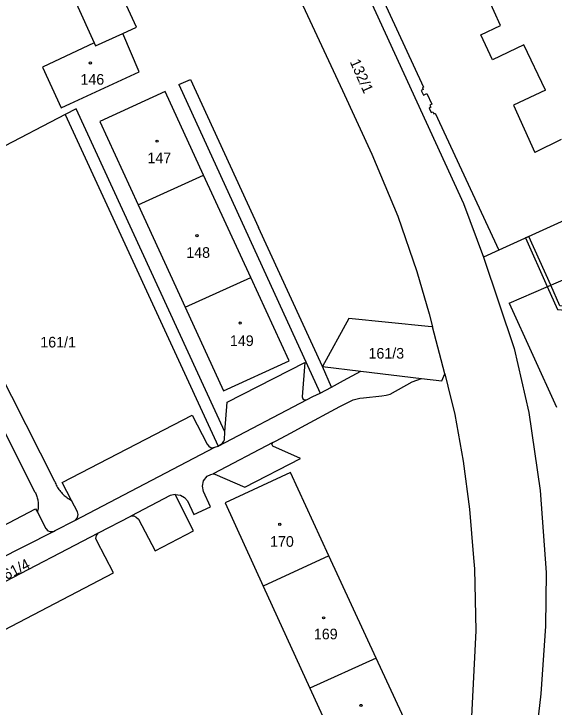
# Model space of a CAD drawing. Extents: x -869103 to -863415, y -1015889 to -1012477.
# Drawn here: x -867078.6 to -866992.3, y -1013913 to -1013802.3 of the extents above; entities that cross this region are included whole.
import ezdxf

# ---------------------------------------------------------------- set-up
doc = ezdxf.new("R2010")
doc.units = 0
for name, color, linetype in [('Hranice parcel', 7, 'Continuous'), ('Parcelní čísla', 7, 'Continuous'), ('Vnitřní kresba', 7, 'Continuous'), ('Věcná břemena k části', 7, 'Continuous'), ('Značky budov', 7, 'Continuous')]:
    doc.layers.add(name, color=color, linetype=linetype)

msp = doc.modelspace()

# ---------------------------------------------------------------- linework, layer by layer
at = {"layer": 'Hranice parcel'}
for p, q in [((-867011.35, -1013818.15), (-867001.17, -1013840.01)), ((-867058.76, -1013832.77), (-867048.3, -1013828.03)), ((-867040.77, -1013844.38), (-867048.3, -1013828.03)), ((-867058.76, -1013832.77), (-867051.25, -1013849.15)), ((-867001.17, -1013840.01), (-867003.6, -1013841.12)), ((-867003.6, -1013841.12), (-866998.7, -1013855.71)), ((-867051.25, -1013849.15), (-867040.77, -1013844.38)), ((-867009.8, -1013859.76), (-867011.73, -1013852.29)), ((-867023.17, -1013859.35), (-867013.48, -1013860.52)), ((-867028.29, -1013888.85), (-867038.77, -1013893.68)), ((-867020.72, -1013905.22), (-867028.29, -1013888.85)), ((-867038.77, -1013893.68), (-867031.32, -1013909.98)), ((-867020.72, -1013905.22), (-867031.32, -1013909.98)), ((-867031.32, -1013909.98), (-867025.25, -1013923.25))]:
    msp.add_line(p, q, dxfattribs=at)
for points in [[(-867042.25, -1013755.23), (-867006.81, -1013832.56), (-867003.6, -1013841.12)], [(-867048.05, -1013767.44), (-867026.12, -1013814.51), (-867021.45, -1013824.68), (-867017.3, -1013834.61), (-867014.25, -1013843.43), (-867012.27, -1013850.21), (-867011.73, -1013852.29)], [(-867026.8, -1013784.47), (-867013.18, -1013814), (-867013.36, -1013814.08), (-867013.23, -1013814.36), (-867013.54, -1013814.51), (-867013.2, -1013815.25), (-867012.67, -1013815), (-867011.86, -1013816.72), (-867012.18, -1013816.87), (-867012.03, -1013817.19), (-867012.3, -1013817.32), (-867011.96, -1013818.05), (-867011.68, -1013817.92), (-867011.53, -1013818.23), (-867011.35, -1013818.15)], [(-867061.18, -1013805.39), (-867059.01, -1013804.41), (-867064.82, -1013791.8), (-867071.27, -1013794.74), (-867065.78, -1013806.91)], [(-867065.78, -1013806.91), (-867074.04, -1013810.81), (-867071.06, -1013817.29), (-867058.57, -1013811.54), (-867061.18, -1013805.39)], [(-867065.78, -1013806.91), (-867065.57, -1013807.37), (-867061.18, -1013805.39)], [(-867048.3, -1013828.03), (-867054.45, -1013814.69), (-867064.88, -1013819.45), (-867058.76, -1013832.77)], [(-866982.03, -1013832.14), (-866982.16, -1013831.83), (-866982.94, -1013832.18), (-866983.06, -1013831.91), (-866985.88, -1013833.22), (-866985.94, -1013833.08), (-867001.17, -1013840.01)], [(-867051.25, -1013849.15), (-867045.13, -1013862.47), (-867034.64, -1013857.69), (-867040.77, -1013844.38)], [(-867011.73, -1013852.29), (-867012.45, -1013852.24), (-867025.09, -1013850.96), (-867029.34, -1013858.6), (-867023.17, -1013859.35)], [(-866998.7, -1013855.71), (-866996.34, -1013865.97), (-866994.56, -1013878.41), (-866993.62, -1013891.49), (-866993.7, -1013900.09), (-866994.44, -1013910.9), (-866995.16, -1013916.92), (-866995.81, -1013921.84), (-866996.12, -1013923.64)], [(-867090.02, -1013889.1), (-867075.13, -1013881.35), (-867074.85, -1013881.88), (-867073.5, -1013884.47), (-867073.2, -1013884.85), (-867072.82, -1013884.99), (-867072.28, -1013884.94), (-867072.03, -1013884.81), (-867068.86, -1013883.19), (-867068.43, -1013882.74), (-867068.33, -1013882.24), (-867068.42, -1013881.84), (-867069.38, -1013879.99), (-867070.87, -1013877.13), (-867050.12, -1013866.39), (-867047.72, -1013871), (-867047.48, -1013871.34), (-867047.07, -1013871.58), (-867046.5, -1013871.51), (-867045.97, -1013871.32), (-867045.28, -1013870.86), (-867045.06, -1013870.56), (-867044.96, -1013870.32), (-867044.89, -1013869.06), (-867044.55, -1013864.33), (-867032.12, -1013857.96), (-867032.55, -1013863.48), (-867032.45, -1013863.79), (-867032.21, -1013863.92), (-867031.77, -1013863.86), (-867030.87, -1013863.4), (-867029.7, -1013862.89), (-867027.89, -1013861.91), (-867025.96, -1013860.87), (-867023.17, -1013859.35)], [(-867084.85, -1013903.1), (-867062.72, -1013891.58), (-867065.37, -1013886.45), (-867065.49, -1013886.07), (-867065.41, -1013885.62), (-867065.1, -1013885.18), (-867059.9, -1013882.52), (-867059.46, -1013882.45), (-867059.05, -1013882.66), (-867058.71, -1013883), (-867056.02, -1013888.08), (-867049.92, -1013884.86), (-867052.83, -1013879.05), (-867052, -1013879.15), (-867051.33, -1013879.52), (-867050.9, -1013880.07), (-867049.87, -1013882.26), (-867047.2, -1013881.02), (-867048.33, -1013878.57), (-867048.49, -1013877.73), (-867048.31, -1013876.87), (-867047.76, -1013876.13), (-867047.15, -1013875.86), (-867046.79, -1013875.74), (-867046.5, -1013875.82), (-867041.73, -1013877.89), (-867032.85, -1013873.29), (-867037.24, -1013871.34), (-867037.41, -1013871.02), (-867037.26, -1013870.77), (-867036.84, -1013870.55), (-867034.33, -1013869.21), (-867032.65, -1013868.3), (-867026.53, -1013865.01), (-867024.41, -1013863.94), (-867023.37, -1013863.68), (-867022.79, -1013863.62), (-867019.83, -1013863.32), (-867019.14, -1013863.18), (-867018.52, -1013863.01), (-867015.01, -1013861.08), (-867013.48, -1013860.52)], [(-867013.48, -1013860.52), (-867010.27, -1013860.91), (-867009.8, -1013859.76)], [(-867009.8, -1013859.76), (-867009.29, -1013861.74), (-867008.19, -1013866.29), (-867006.84, -1013873.72), (-867005.84, -1013881.41), (-867005.21, -1013889.19), (-867005.04, -1013890.94), (-867004.84, -1013900.83), (-867005.57, -1013915.59), (-867005.81, -1013918.17)], [(-867028.29, -1013888.85), (-867034.45, -1013875.55), (-867044.84, -1013880.41), (-867038.77, -1013893.68)], [(-867017.17, -1013919.59), (-867014.56, -1013918.53), (-867020.72, -1013905.22)]]:
    msp.add_lwpolyline(points, dxfattribs=at)
at = {"layer": 'Vnitřní kresba'}
for p, q in [((-867000.87, -1013804.15), (-867005.61, -1013793.69)), ((-867004.04, -1013805.62), (-867000.87, -1013804.15)), ((-867002.18, -1013809.61), (-867004.04, -1013805.62)), ((-866997.16, -1013807.24), (-867002.18, -1013809.61)), ((-866993.7, -1013814.48), (-866997.16, -1013807.24)), ((-867052.28, -1013813.58), (-867050.41, -1013812.74)), ((-867050.41, -1013812.74), (-867039.56, -1013836.43)), ((-867052.28, -1013813.58), (-867029.7, -1013862.89)), ((-866993.7, -1013814.48), (-866998.82, -1013816.86)), ((-866998.82, -1013816.86), (-866995.4, -1013824.42)), ((-867070.42, -1013818.35), (-867089.39, -1013828.27)), ((-867068.67, -1013817.45), (-867070.42, -1013818.35)), ((-867070.42, -1013818.35), (-867045.97, -1013871.32)), ((-867044.89, -1013869.06), (-867068.67, -1013817.45)), ((-866991.22, -1013822.35), (-866995.4, -1013824.42)), ((-867072.08, -1013876.99), (-867092.24, -1013837.2)), ((-867029.34, -1013858.6), (-867039.56, -1013836.43)), ((-867075.2, -1013878.73), (-867095.55, -1013838.49)), ((-866999.49, -1013848.5), (-866987.42, -1013843.24)), ((-866999.49, -1013848.5), (-866991.96, -1013865.11)), ((-867027.89, -1013861.91), (-867029.34, -1013858.6)), ((-867045.97, -1013871.32), (-867031.77, -1013863.86)), ((-867068.86, -1013883.19), (-867046.5, -1013871.51)), ((-867037.26, -1013870.77), (-867046.79, -1013875.74)), ((-867053.62, -1013879.2), (-867059.9, -1013882.52)), ((-867052.83, -1013879.05), (-867053.62, -1013879.2)), ((-867088.37, -1013893.15), (-867072.28, -1013884.94)), ((-867088.63, -1013897.43), (-867065.1, -1013885.18))]:
    msp.add_line(p, q, dxfattribs=at)
for points in [[(-867072.08, -1013876.99), (-867072.01, -1013877.18), (-867071.92, -1013877.37), (-867071.83, -1013877.56), (-867071.74, -1013877.74), (-867071.63, -1013877.92), (-867071.52, -1013878.09), (-867071.41, -1013878.27), (-867071.28, -1013878.43), (-867071.15, -1013878.59), (-867071.02, -1013878.75), (-867070.88, -1013878.9), (-867070.73, -1013879.05), (-867070.58, -1013879.19), (-867070.42, -1013879.32), (-867070.26, -1013879.45), (-867070.09, -1013879.57), (-867069.92, -1013879.69), (-867069.74, -1013879.79), (-867069.56, -1013879.9), (-867069.38, -1013879.99)], [(-867075.2, -1013878.73), (-867075.12, -1013878.89), (-867075.05, -1013879.06), (-867074.98, -1013879.22), (-867074.93, -1013879.4), (-867074.87, -1013879.57), (-867074.83, -1013879.74), (-867074.79, -1013879.92), (-867074.76, -1013880.09), (-867074.74, -1013880.27), (-867074.72, -1013880.45), (-867074.71, -1013880.63), (-867074.71, -1013880.81), (-867074.72, -1013880.99), (-867074.73, -1013881.17), (-867074.75, -1013881.35), (-867074.78, -1013881.53), (-867074.81, -1013881.71), (-867074.85, -1013881.88)]]:
    msp.add_lwpolyline(points, dxfattribs=at)
at = {"layer": 'Věcná břemena k části'}
msp.add_lwpolyline([(-866996.35, -1013837.82), (-866996.89, -1013838.06), (-866993.42, -1013845.85), (-866991.79, -1013849.5), (-866985.54, -1013850.01), (-866985.26, -1013850.03), (-866975.28, -1013850.91), (-866974.87, -1013850.37), (-866975.19, -1013850.31), (-866985.2, -1013849.43), (-866985.33, -1013849.42), (-866991.39, -1013848.94), (-866992.87, -1013845.62)], close=True, dxfattribs=at)
at = {"layer": 'Značky budov'}
for centre in [(-867066.38, -1013810.12), (-867055.73, -1013822.62), (-867049.37, -1013837.71), (-867042.46, -1013851.66), (-867036.14, -1013883.83), (-867029.14, -1013898.75), (-867023.18, -1013912.75)]:
    msp.add_circle(centre, 0.175, dxfattribs=at)

# ---------------------------------------------------------------- texts
at = {"layer": 'Parcelní čísla'}
for s, rotation, p in [('132/1', 294, (-867024.99, -1013809.93)), ('161/4', 27, (-867080.92, -1013893.33))]:
    msp.add_text(s, height=1.7, rotation=rotation, dxfattribs=at).set_placement(p)
for s, p in [('146', (-867067.97, -1013813.59)), ('147', (-867057.27, -1013826.13)), ('148', (-867051.07, -1013841.25)), ('161/1', (-867074.38, -1013855.57)), ('149', (-867044.1, -1013855.34)), ('161/3', (-867021.97, -1013857.35)), ('170', (-867037.69, -1013887.41)), ('169', (-867030.69, -1013902.19))]:
    msp.add_text(s, height=1.7, dxfattribs=at).set_placement(p)

doc.saveas('drawing.dxf')
